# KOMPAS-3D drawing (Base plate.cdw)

Views: View 1, Front, View 3, Isometric YZX
Referenced files in C:\Work\01 К О М П А С\Модели примеры\2009_04_For_Poland_AXAPACK\My sample\: Base plate.a3d, Base plate.m3d, rail1.m3d
Referenced files in D:\Documents and Settings\kashirsky\Рабочий стол\: GRAPHIC_DE.LYT
Referenced files: Base plate.cdw
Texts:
  Base plate
  Drawing Annotation
  Dimension Texts
  Surface Finish
  Leader #1
  Leader #2
  Leader #3
  Shape Deviations and Datum
  Table Header
  Table Cell
  Cut/Section Line
  Direction Arrow
  Modification Symbol
  Brace
  Node point number
  Mark of coordination axis
  VRCB
  Leader Text
  Node point designation
  Mark/Reference designation with leader
  Mark/reference designation on line
  Mark/Reference designation without leader
  System Layer
  System View
  Projection View 2
  Specifications
  Unspecified Surface Finish
  BOM table name
  Rail of BP
Dimensions and other numbers on the sheet: 7; 3000; 1700; 1820; 1:1; 1; 1486,79; 0; 2; 3; 4; 5; 6; 8; 9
